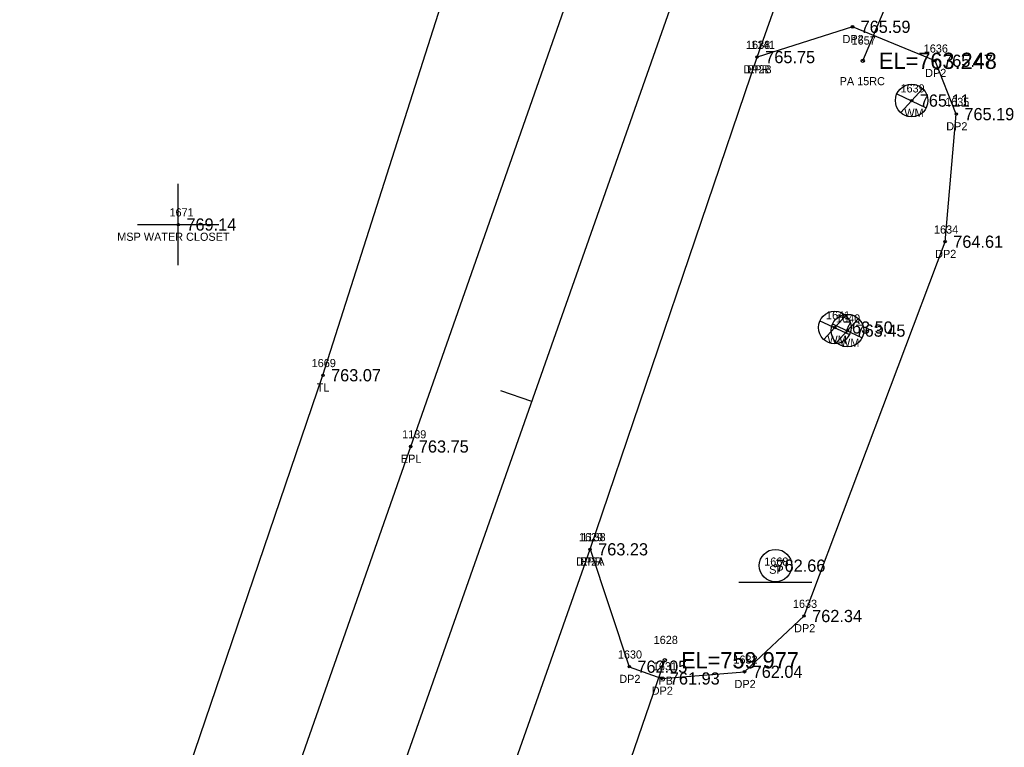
# Model space of a CAD drawing. Extents: x 1736563 to 1738032, y 1150548 to 1154248.
# Drawn here: x 1737676.5 to 1737797.6, y 1153550.8 to 1153640.2 of the extents above; entities that cross this region are included whole.
import ezdxf

# ---------------------------------------------------------------- set-up
doc = ezdxf.new("R2010")
doc.units = 0
for name, color, linetype in [('RD_EX_BldgApp', 7, 'Continuous'), ('RD_EX_BldgApp_txCode', 7, 'Continuous'), ('RD_EX_DR_Pipe', 7, 'Continuous'), ('RD_EX_DR_Pipe_txCode', 7, 'Continuous'), ('RD_EX_Driveway', 7, 'Continuous'), ('RD_EX_Driveway_txCode', 7, 'Continuous'), ('RD_EX_Misc', 7, 'Continuous'), ('RD_EX_Misc_txCode', 7, 'Continuous'), ('RD_EX_Road', 7, 'Continuous'), ('RD_EX_Road_txCode', 7, 'Continuous'), ('RD_EX_TX_BldgApp_ELEV', 7, 'Continuous'), ('RD_EX_TX_Driveway_ELEV', 7, 'Continuous'), ('RD_EX_TX_Misc_ELEV', 7, 'Continuous'), ('RD_EX_TX_Road_ELEV', 7, 'Continuous'), ('RD_EX_TX_UT_ELEV', 7, 'Continuous'), ('RD_EX_TX_VEG_ELEV', 7, 'Continuous'), ('RD_EX_UT', 7, 'Continuous'), ('RD_EX_UT_txCode', 7, 'Continuous'), ('RD_EX_VEG', 7, 'Continuous'), ('RD_EX_VEG_txCode', 7, 'Continuous'), ('RD_HC_Cl', 7, 'Continuous'), ('RD_HC_Data_Tic', 7, 'Continuous'), ('RD_SMD_Locator', 7, 'Continuous'), ('RD_TX_Pipe_ElevEX', 7, 'Continuous')]:
    doc.layers.add(name, color=color, linetype=linetype)

msp = doc.modelspace()

# ---------------------------------------------------------------- linework, layer by layer
at = {"layer": 'RD_EX_BldgApp'}
msp.add_line((1737764.97, 1153571.07), (1737773.97, 1153571.07), dxfattribs=at)
msp.add_circle((1737769.49, 1153573.1), 2, dxfattribs=at)
at = {"layer": 'RD_EX_DR_Pipe'}
for p, q in [((1737780.22, 1153635.17), (1737796.1, 1153672.65)), ((1737745.56, 1153531.46), (1737755.87, 1153561.47))]:
    msp.add_line(p, q, dxfattribs=at)
at = {"layer": 'RD_EX_Driveway'}
msp.add_lwpolyline([(1737746.67, 1153575.11), (1737751.5, 1153560.68), (1737755.49, 1153559.23), (1737765.68, 1153560.05), (1737773, 1153566.91), (1737790.36, 1153612.93), (1737791.73, 1153628.62), (1737789.12, 1153635.18), (1737778.96, 1153639.35), (1737767.23, 1153635.63)], dxfattribs=at)
at = {"layer": 'RD_EX_Misc'}
for p, q in [((1737696.01, 1153610.04), (1737696.01, 1153620.04)), ((1737691.01, 1153615.04), (1737701.01, 1153615.04))]:
    msp.add_line(p, q, dxfattribs=at)
at = {"layer": 'RD_EX_Road'}
for points in [[(1737496.36, 1152940.55), (1737529.37, 1153032.75), (1737537.93, 1153057.4), (1737549.32, 1153089.17), (1737563.01, 1153127.73), (1737595.49, 1153219.95), (1737628.15, 1153312.67), (1737660.2, 1153403.8), (1737692.32, 1153495.67), (1737724.61, 1153587.75), (1737756.73, 1153679.29), (1737770.32, 1153718.5), (1737778.01, 1153740.46), (1737788.96, 1153772.48), (1737822.56, 1153867.79), (1737856.1, 1153962.19), (1737875.63, 1154016.18), (1737880.55, 1154030.08), (1737889.82, 1154055.89), (1737923.73, 1154151.97)], [(1737552.4, 1153024.11), (1737569.73, 1153074.37), (1737580.02, 1153102.83), (1737585.88, 1153119.72), (1737600.61, 1153161.43), (1737609.53, 1153186.52), (1737618.32, 1153211.94), (1737651.18, 1153304.47), (1737683.4, 1153395.05), (1737705.88, 1153458.65), (1737715.8, 1153487.43), (1737725.08, 1153513.79), (1737730.46, 1153529.07), (1737746.67, 1153575.11), (1737767.23, 1153635.63), (1737779.62, 1153670.7)]]:
    msp.add_lwpolyline(points, dxfattribs=at)
at = {"layer": 'RD_EX_UT'}
for p, q in [((1737784.41, 1153631.11), (1737788.04, 1153629.4)), ((1737784.89, 1153628.82), (1737787.56, 1153631.72)), ((1737774.95, 1153603.22), (1737778.58, 1153601.51)), ((1737775.43, 1153600.92), (1737778.1, 1153603.82)), ((1737776.51, 1153602.84), (1737780.14, 1153601.13)), ((1737776.99, 1153600.55), (1737779.66, 1153603.44))]:
    msp.add_line(p, q, dxfattribs=at)
for centre in [(1737786.24, 1153630.28), (1737776.78, 1153602.38), (1737778.34, 1153602)]:
    msp.add_circle(centre, 2, dxfattribs=at)
at = {"layer": 'RD_EX_VEG'}
msp.add_lwpolyline([(1737451.48, 1152925.19), (1737471.83, 1152967.5), (1737483.5, 1153062.03), (1737523.53, 1153143.47), (1737578.4, 1153225.34), (1737613.35, 1153318.74), (1737643.94, 1153407.18), (1737681, 1153500.22), (1737713.81, 1153596.51), (1737742.54, 1153686.46), (1737776.37, 1153777.24), (1737812.9, 1153871.37), (1737847.32, 1153964.45), (1737872.45, 1154065.49)], dxfattribs=at)
at = {"layer": 'RD_HC_Cl'}
msp.add_line((1736879.96, 1151154.46), (1737935.1, 1154148.31), dxfattribs=at)
at = {"layer": 'RD_HC_Data_Tic'}
msp.add_line((1737739.49, 1153593.27), (1737735.71, 1153594.6), dxfattribs=at)
at = {"layer": 'RD_SMD_Locator'}
for centre, radius in [((1737778.96, 1153639.35), 0.15), ((1737767.23, 1153635.63), 0.15), ((1737767.23, 1153635.63), 0.15), ((1737780.22, 1153635.17), 0.2), ((1737789.12, 1153635.18), 0.15), ((1737786.24, 1153630.28), 0.15), ((1737791.73, 1153628.62), 0.15), ((1737696.01, 1153615.04), 0.15), ((1737790.36, 1153612.93), 0.15), ((1737776.78, 1153602.38), 0.15), ((1737778.34, 1153602), 0.15), ((1737713.81, 1153596.51), 0.15), ((1737724.61, 1153587.75), 0.15), ((1737746.67, 1153575.11), 0.15), ((1737746.67, 1153575.11), 0.15), ((1737769.49, 1153573.1), 0.15), ((1737773, 1153566.91), 0.15), ((1737755.87, 1153561.47), 0.2), ((1737751.5, 1153560.68), 0.15), ((1737755.49, 1153559.23), 0.15), ((1737765.68, 1153560.05), 0.15)]:
    msp.add_circle(centre, radius, dxfattribs=at)

# ---------------------------------------------------------------- texts
at = {"layer": 'RD_EX_BldgApp_txCode'}
for s, p in [('1668', (1737768.1, 1153573.1)), ('SP', (1737768.71, 1153572.1))]:
    msp.add_text(s, height=1, dxfattribs=at).set_placement(p)
at = {"layer": 'RD_EX_DR_Pipe_txCode'}
for s, p in [('1657', (1737778.85, 1153637.17)), ('PA 15RC', (1737777.38, 1153632.17)), ('1628', (1737754.5, 1153563.47)), ('PB', (1737755.09, 1153558.47))]:
    msp.add_text(s, height=1, dxfattribs=at).set_placement(p)
at = {"layer": 'RD_EX_Driveway_txCode'}
for s, p in [('DP2', (1737777.74, 1153637.35)), ('1638', (1737765.86, 1153636.63)), ('1636', (1737787.73, 1153636.18)), ('DP2B', (1737765.53, 1153633.63)), ('DP2', (1737787.9, 1153633.18)), ('1635', (1737790.36, 1153629.62)), ('DP2', (1737790.5, 1153626.62)), ('1634', (1737788.99, 1153613.93)), ('DP2', (1737789.13, 1153610.93)), ('1629', (1737745.3, 1153576.11)), ('DP2A', (1737744.96, 1153573.11)), ('1633', (1737771.63, 1153567.91)), ('DP2', (1737771.78, 1153564.91)), ('1630', (1737750.09, 1153561.68)), ('1632', (1737764.31, 1153561.05)), ('1631', (1737754.4, 1153560.23)), ('DP2', (1737750.27, 1153558.68)), ('DP2', (1737754.26, 1153557.23)), ('DP2', (1737764.45, 1153558.05))]:
    msp.add_text(s, height=1, dxfattribs=at).set_placement(p)
at = {"layer": 'RD_EX_Misc_txCode'}
for s, p in [('1671', (1737694.93, 1153616.04)), ('MSP WATER CLOSET', (1737688.5, 1153613.04))]:
    msp.add_text(s, height=1, dxfattribs=at).set_placement(p)
at = {"layer": 'RD_EX_Road_txCode'}
for s, p in [('1141', (1737766.45, 1153636.63)), ('EPR', (1737766, 1153633.63)), ('1139', (1737723.55, 1153588.75)), ('EPL', (1737723.4, 1153585.75)), ('1138', (1737745.61, 1153576.11)), ('EPR', (1737745.45, 1153573.11))]:
    msp.add_text(s, height=1, dxfattribs=at).set_placement(p)
at = {"layer": 'RD_EX_TX_BldgApp_ELEV'}
msp.add_text('762.66', height=1.5, dxfattribs=at).set_placement((1737769.49, 1153572.35))
at = {"layer": 'RD_EX_TX_Driveway_ELEV'}
for s, p in [('765.59', (1737779.96, 1153638.6)), ('765.75', (1737768.23, 1153634.88)), ('765.47', (1737790.12, 1153634.43)), ('765.19', (1737792.73, 1153627.87)), ('764.61', (1737791.36, 1153612.18)), ('763.23', (1737747.67, 1153574.36)), ('762.34', (1737774, 1153566.16)), ('762.05', (1737752.5, 1153559.93)), ('762.04', (1737766.68, 1153559.3)), ('761.93', (1737756.49, 1153558.48))]:
    msp.add_text(s, height=1.5, dxfattribs=at).set_placement(p)
at = {"layer": 'RD_EX_TX_Misc_ELEV'}
msp.add_text('769.14', height=1.5, dxfattribs=at).set_placement((1737697.01, 1153614.29))
at = {"layer": 'RD_EX_TX_Road_ELEV'}
for s, p in [('765.75', (1737768.23, 1153634.88)), ('763.75', (1737725.61, 1153587)), ('763.23', (1737747.67, 1153574.36))]:
    msp.add_text(s, height=1.5, dxfattribs=at).set_placement(p)
at = {"layer": 'RD_EX_TX_UT_ELEV'}
for s, p in [('765.11', (1737787.24, 1153629.53)), ('763.50', (1737777.78, 1153601.63)), ('763.45', (1737779.34, 1153601.25))]:
    msp.add_text(s, height=1.5, dxfattribs=at).set_placement(p)
at = {"layer": 'RD_EX_TX_VEG_ELEV'}
msp.add_text('763.07', height=1.5, dxfattribs=at).set_placement((1737714.81, 1153595.76))
at = {"layer": 'RD_EX_UT_txCode'}
for s, p in [('1639', (1737784.87, 1153631.28)), ('WM', (1737785.34, 1153628.28)), ('1641', (1737775.7, 1153603.38)), ('1640', (1737776.93, 1153603)), ('WM', (1737775.88, 1153600.38)), ('WM', (1737777.43, 1153600))]:
    msp.add_text(s, height=1, dxfattribs=at).set_placement(p)
at = {"layer": 'RD_EX_VEG_txCode'}
for s, p in [('1669', (1737712.42, 1153597.51)), ('TL', (1737713.04, 1153594.51))]:
    msp.add_text(s, height=1, dxfattribs=at).set_placement(p)
at = {"layer": 'RD_TX_Pipe_ElevEX'}
for s, p in [('EL=763.248', (1737782.22, 1153634.17)), ('EL=759.977', (1737757.87, 1153560.47))]:
    msp.add_text(s, height=2, dxfattribs=at).set_placement(p)

doc.saveas('drawing.dxf')
